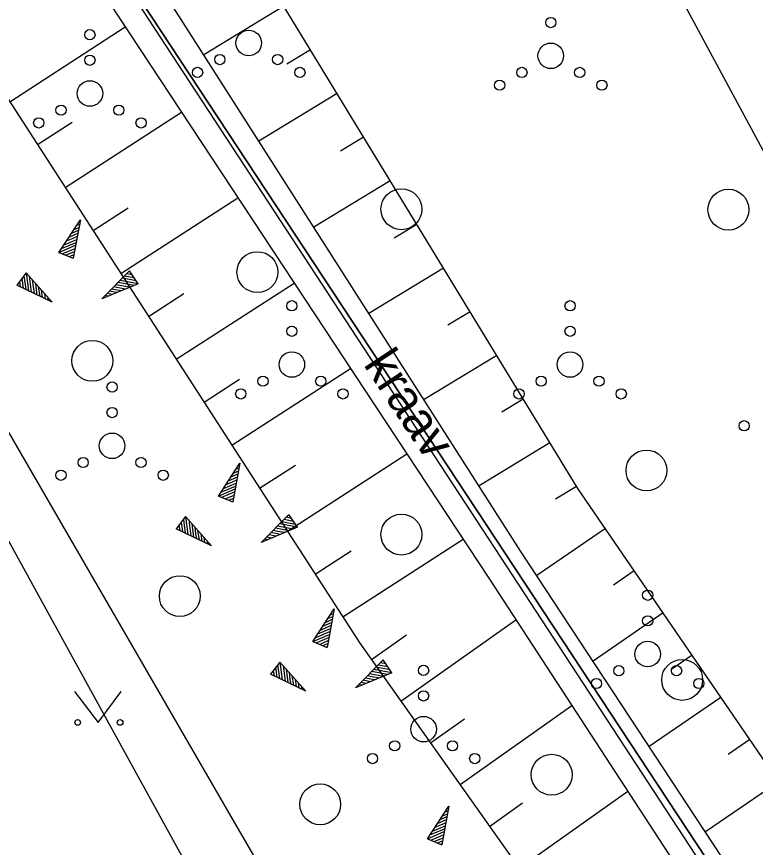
# Model space of a CAD drawing. Extents: x 554947 to 555436, y 6564938 to 6565792.
# Drawn here: x 555242.09 to 555256.53, y 6565114.23 to 6565130.48 of the extents above; entities that cross this region are included whole.
import ezdxf

# ---------------------------------------------------------------- set-up
doc = ezdxf.new("R2010")
doc.units = 0
for name, color, linetype in [('HALJASTUS', 7, 'Continuous'), ('MPKAABEL', 7, 'Continuous'), ('PIIR', 7, 'Continuous'), ('RELJEEF', 7, 'Continuous'), ('VEEKOGU', 7, 'Continuous')]:
    doc.layers.add(name, color=color, linetype=linetype)

msp = doc.modelspace()

# ---------------------------------------------------------------- linework, layer by layer
at = {"layer": 'HALJASTUS'}
for p, q in [((555243.221, 6565117.279), (555243.684, 6565116.673)), ((555243.684, 6565116.673), (555244.13, 6565117.279))]:
    msp.add_line(p, q, dxfattribs=at)
for points in [[(555235.12, 6565151.155), (555232.135, 6565148.949), (555229.151, 6565146.49), (555228.521, 6565144.196), (555233.66, 6565136.637), (555246.422, 6565114.586), (555255.514, 6565098.946)], [(555277.06, 6565106.584), (555277.255, 6565111.788), (555268.557, 6565110.949), (555265.778, 6565110.936), (555262.384, 6565108.727), (555261.075, 6565113.375), (555263.858, 6565115.236), (555262.795, 6565117.659), (555261.001, 6565121.133), (555260.129, 6565122.751), (555257.76, 6565125.864), (555253.762, 6565133.295), (555248.914, 6565136.251)]]:
    msp.add_lwpolyline(points, dxfattribs=at)
for centre, radius in [((555252.534, 6565130.359), 0.1), ((555243.522, 6565130.122), 0.1), ((555246.628, 6565129.96), 0.25), ((555252.534, 6565129.709), 0.25), ((555243.522, 6565129.622), 0.1), ((555246.063, 6565129.635), 0.1), ((555247.193, 6565129.635), 0.1), ((555245.628, 6565129.385), 0.1), ((555247.628, 6565129.385), 0.1), ((555251.969, 6565129.384), 0.1), ((555253.099, 6565129.384), 0.1), ((555243.522, 6565128.972), 0.25), ((555251.534, 6565129.134), 0.1), ((555253.534, 6565129.134), 0.1), ((555242.957, 6565128.647), 0.1), ((555244.087, 6565128.647), 0.1), ((555242.522, 6565128.397), 0.1), ((555244.522, 6565128.397), 0.1), ((555249.614, 6565126.709), 0.4), ((555256.007, 6565126.7), 0.4), ((555246.797, 6565125.479), 0.4), ((555247.471, 6565124.822), 0.1), ((555252.912, 6565124.822), 0.1), ((555247.471, 6565124.322), 0.1), ((555252.912, 6565124.322), 0.1), ((555243.57, 6565123.744), 0.4), ((555247.471, 6565123.672), 0.25), ((555252.912, 6565123.672), 0.25), ((555243.956, 6565123.232), 0.1), ((555246.906, 6565123.347), 0.1), ((555248.036, 6565123.347), 0.1), ((555252.347, 6565123.347), 0.1), ((555253.477, 6565123.347), 0.1), ((555246.471, 6565123.097), 0.1), ((555248.471, 6565123.097), 0.1), ((555251.912, 6565123.097), 0.1), ((555253.912, 6565123.097), 0.1), ((555243.956, 6565122.732), 0.1), ((555256.315, 6565122.475), 0.1), ((555243.956, 6565122.082), 0.25), ((555254.405, 6565121.6), 0.4), ((555243.391, 6565121.757), 0.1), ((555244.521, 6565121.757), 0.1), ((555242.956, 6565121.507), 0.1), ((555244.956, 6565121.507), 0.1), ((555249.614, 6565120.347), 0.4), ((555245.28, 6565119.143), 0.4), ((555254.429, 6565119.16), 0.1), ((555254.429, 6565118.66), 0.1), ((555254.429, 6565118.01), 0.25), ((555255.103, 6565117.505), 0.4), ((555250.047, 6565117.691), 0.1), ((555253.864, 6565117.685), 0.1), ((555254.994, 6565117.685), 0.1), ((555253.429, 6565117.435), 0.1), ((555255.429, 6565117.435), 0.1), ((555250.047, 6565117.191), 0.1), ((555243.283, 6565116.673), 0.055), ((555244.112, 6565116.673), 0.055), ((555250.047, 6565116.541), 0.25), ((555249.482, 6565116.216), 0.1), ((555250.612, 6565116.216), 0.1), ((555249.047, 6565115.966), 0.1), ((555251.047, 6565115.966), 0.1), ((555252.551, 6565115.65), 0.4), ((555248.025, 6565115.071), 0.4)]:
    msp.add_circle(centre, radius, dxfattribs=at)
at = {"layer": 'MPKAABEL'}
msp.add_lwpolyline([(555252.588, 6565101.946), (555250.157, 6565105.485), (555246.43, 6565112.048), (555243.328, 6565117.686), (555240.248, 6565123.284), (555235.885, 6565131.607), (555233.393, 6565136.173), (555233.034, 6565137.981), (555233.62, 6565138.358), (555237.1, 6565137.907), (555242.704, 6565136.954), (555245.573, 6565136.455), (555256.506, 6565134.49), (555262.887, 6565133.288), (555269.268, 6565132.087), (555280.849, 6565129.896), (555289.168, 6565128.301), (555288.207, 6565123.189), (555286.959, 6565118.589), (555293.983, 6565117.646), (555297.167, 6565117.091)], dxfattribs=at)
at = {"layer": 'PIIR'}
for points in [[(555293.54, 6565286.23), (555256.63, 6565245.54), (555254.61, 6565228.5), (555255.75, 6565226.79), (555261.42, 6565218.27), (555289.11, 6565186.6), (555315.28, 6565149.09), (555315.73, 6565134.86), (555310.07, 6565124.47), (555303.59, 6565115.89), (555291.54, 6565100.48), (555288.85, 6565092.31), (555275.41, 6565088.83), (555273.15, 6565087.34), (555239.11, 6565139), (555231.12, 6565150.64), (555225.89, 6565157.13), (555173.21, 6565166.35), (555173.84, 6565168.77), (555191.64, 6565237.48), (555195.28, 6565271.63)], [(555272.013, 6565013.369), (555140.74, 6565041.04), (555172.58, 6565163.93), (555173.21, 6565166.35), (555225.89, 6565157.13), (555231.12, 6565150.64), (555239.11, 6565139), (555273.15, 6565087.34), (555275.41, 6565088.83), (555288.85, 6565092.31), (555289.83, 6565088.53), (555290.166, 6565088.221)]]:
    msp.add_lwpolyline(points, dxfattribs=at)
at = {"layer": 'RELJEEF'}
for p, q in [((555247.314, 6565130.683), (555245.748, 6565129.729)), ((555241.954, 6565128.812), (555244.214, 6565130.273)), ((555247.834, 6565129.829), (555247.37, 6565129.546)), ((555248.355, 6565128.975), (555246.825, 6565128.043)), ((555243.04, 6565127.133), (555245.315, 6565128.604)), ((555242.497, 6565127.973), (555243.177, 6565128.412)), ((555248.875, 6565128.121), (555248.421, 6565127.845)), ((555249.395, 6565127.267), (555247.902, 6565126.357)), ((555244.125, 6565125.453), (555246.416, 6565126.934)), ((555243.583, 6565126.293), (555244.267, 6565126.736)), ((555242.917, 6565125.864), (555243.337, 6565126.504)), ((555243.337, 6565126.504), (555243.197, 6565125.749)), ((555243.262, 6565126.389), (555243.322, 6565126.414)), ((555243.312, 6565126.464), (555243.332, 6565126.474)), ((555249.916, 6565126.413), (555249.473, 6565126.143)), ((555243.167, 6565126.239), (555243.297, 6565126.299)), ((555243.212, 6565126.314), (555243.312, 6565126.354)), ((555243.017, 6565126.014), (555243.267, 6565126.119)), ((555243.067, 6565126.089), (555243.192, 6565126.144)), ((555243.117, 6565126.164), (555243.287, 6565126.239)), ((555243.192, 6565126.144), (555243.277, 6565126.179)), ((555242.917, 6565125.864), (555243.242, 6565126.004)), ((555242.967, 6565125.939), (555243.252, 6565126.059)), ((555242.982, 6565125.839), (555243.232, 6565125.944)), ((555242.917, 6565125.864), (555243.197, 6565125.749)), ((555242.917, 6565125.864), (555242.917, 6565125.864)), ((555243.047, 6565125.809), (555243.222, 6565125.884)), ((555243.117, 6565125.784), (555243.212, 6565125.824)), ((555243.182, 6565125.759), (555243.197, 6565125.764)), ((555242.276, 6565125.463), (555242.091, 6565125.223)), ((555242.276, 6565125.463), (555242.781, 6565124.893)), ((555242.276, 6565125.463), (555242.321, 6565125.113)), ((555242.276, 6565125.463), (555242.276, 6565125.463)), ((555243.755, 6565124.958), (555244.295, 6565125.503)), ((555244.345, 6565125.428), (555244.245, 6565125.448)), ((555244.305, 6565125.488), (555244.285, 6565125.488)), ((555244.465, 6565125.253), (555244.295, 6565125.503)), ((555250.436, 6565125.559), (555248.978, 6565124.671)), ((555242.146, 6565125.293), (555242.161, 6565125.193)), ((555242.191, 6565125.353), (555242.216, 6565125.168)), ((555242.231, 6565125.408), (555242.266, 6565125.138)), ((555242.336, 6565125.398), (555242.376, 6565125.088)), ((555242.396, 6565125.328), (555242.431, 6565125.063)), ((555244.38, 6565125.218), (555244.075, 6565125.278)), ((555244.465, 6565125.253), (555244.115, 6565125.318)), ((555244.425, 6565125.308), (555244.16, 6565125.363)), ((555244.385, 6565125.368), (555244.2, 6565125.403)), ((555242.781, 6565124.893), (555242.091, 6565125.223)), ((555242.101, 6565125.238), (555242.106, 6565125.218)), ((555242.456, 6565125.263), (555242.471, 6565125.123)), ((555242.471, 6565125.123), (555242.486, 6565125.033)), ((555242.511, 6565125.193), (555242.541, 6565125.008)), ((555242.571, 6565125.128), (555242.591, 6565124.983)), ((555244.465, 6565125.253), (555243.755, 6565124.958)), ((555244.045, 6565125.078), (555243.905, 6565125.108)), ((555244.13, 6565125.113), (555243.945, 6565125.148)), ((555244.08, 6565125.173), (555243.99, 6565125.193)), ((555244.295, 6565125.183), (555244.03, 6565125.233)), ((555244.215, 6565125.148), (555244.08, 6565125.173)), ((555244.465, 6565125.253), (555244.465, 6565125.253)), ((555245.211, 6565123.774), (555247.517, 6565125.264)), ((555242.631, 6565125.058), (555242.646, 6565124.958)), ((555242.691, 6565124.993), (555242.701, 6565124.928)), ((555243.795, 6565124.973), (555243.78, 6565124.978)), ((555243.88, 6565125.008), (555243.82, 6565125.023)), ((555243.965, 6565125.043), (555243.86, 6565125.063)), ((555244.668, 6565124.613), (555245.358, 6565125.059)), ((555242.751, 6565124.923), (555242.756, 6565124.903)), ((555250.956, 6565124.705), (555250.524, 6565124.442)), ((555251.477, 6565123.851), (555250.055, 6565122.985)), ((555246.297, 6565122.094), (555248.619, 6565123.595)), ((555245.754, 6565122.934), (555246.448, 6565123.383)), ((555251.997, 6565122.997), (555251.576, 6565122.741)), ((555252.517, 6565122.143), (555251.132, 6565121.299)), ((555247.383, 6565120.414), (555249.72, 6565121.925)), ((555246.035, 6565121.1), (555246.455, 6565121.74)), ((555246.455, 6565121.74), (555246.315, 6565120.985)), ((555246.43, 6565121.7), (555246.45, 6565121.71)), ((555246.84, 6565121.254), (555247.539, 6565121.706)), ((555246.285, 6565121.475), (555246.415, 6565121.535)), ((555246.33, 6565121.55), (555246.43, 6565121.59)), ((555246.38, 6565121.625), (555246.44, 6565121.65)), ((555246.185, 6565121.325), (555246.31, 6565121.38)), ((555246.235, 6565121.4), (555246.405, 6565121.475)), ((555246.31, 6565121.38), (555246.395, 6565121.415)), ((555246.035, 6565121.1), (555246.36, 6565121.24)), ((555246.085, 6565121.175), (555246.37, 6565121.295)), ((555246.135, 6565121.25), (555246.385, 6565121.355)), ((555253.038, 6565121.289), (555252.627, 6565121.039)), ((555246.035, 6565121.1), (555246.315, 6565120.985)), ((555246.035, 6565121.1), (555246.035, 6565121.1)), ((555246.1, 6565121.075), (555246.35, 6565121.18)), ((555246.165, 6565121.045), (555246.34, 6565121.12)), ((555246.235, 6565121.02), (555246.33, 6565121.06)), ((555246.3, 6565120.995), (555246.315, 6565121)), ((555246.873, 6565120.194), (555247.413, 6565120.739)), ((555247.423, 6565120.724), (555247.403, 6565120.724)), ((555247.583, 6565120.489), (555247.413, 6565120.739)), ((555245.394, 6565120.699), (555245.209, 6565120.459)), ((555245.309, 6565120.589), (555245.334, 6565120.404)), ((555245.349, 6565120.644), (555245.384, 6565120.374)), ((555245.394, 6565120.699), (555245.899, 6565120.129)), ((555245.394, 6565120.699), (555245.439, 6565120.349)), ((555245.394, 6565120.699), (555245.394, 6565120.699)), ((555245.454, 6565120.634), (555245.494, 6565120.324)), ((555245.514, 6565120.564), (555245.549, 6565120.299)), ((555247.543, 6565120.544), (555247.278, 6565120.599)), ((555247.503, 6565120.604), (555247.318, 6565120.639)), ((555247.463, 6565120.664), (555247.363, 6565120.684)), ((555245.899, 6565120.129), (555245.209, 6565120.459)), ((555245.219, 6565120.474), (555245.224, 6565120.454)), ((555245.264, 6565120.529), (555245.279, 6565120.429)), ((555245.574, 6565120.499), (555245.589, 6565120.359)), ((555245.629, 6565120.429), (555245.659, 6565120.244)), ((555247.583, 6565120.489), (555246.873, 6565120.194)), ((555247.198, 6565120.409), (555247.108, 6565120.429)), ((555247.413, 6565120.419), (555247.148, 6565120.469)), ((555247.498, 6565120.454), (555247.193, 6565120.514)), ((555247.333, 6565120.384), (555247.198, 6565120.409)), ((555247.583, 6565120.489), (555247.233, 6565120.554)), ((555247.583, 6565120.489), (555247.583, 6565120.489)), ((555253.601, 6565120.463), (555252.262, 6565119.545)), ((555245.589, 6565120.359), (555245.604, 6565120.269)), ((555245.689, 6565120.364), (555245.709, 6565120.219)), ((555245.749, 6565120.294), (555245.764, 6565120.194)), ((555246.998, 6565120.244), (555246.938, 6565120.259)), ((555247.083, 6565120.279), (555246.978, 6565120.299)), ((555247.163, 6565120.314), (555247.023, 6565120.344)), ((555247.248, 6565120.349), (555247.063, 6565120.384)), ((555248.469, 6565118.735), (555250.821, 6565120.256)), ((555245.809, 6565120.229), (555245.819, 6565120.164)), ((555245.869, 6565120.159), (555245.874, 6565120.139)), ((555246.913, 6565120.209), (555246.898, 6565120.214)), ((555247.926, 6565119.575), (555248.629, 6565120.029)), ((555254.166, 6565119.638), (555253.76, 6565119.359)), ((555247.879, 6565118.255), (555248.299, 6565118.895)), ((555248.299, 6565118.895), (555248.159, 6565118.14)), ((555248.224, 6565118.78), (555248.284, 6565118.805)), ((555248.274, 6565118.855), (555248.294, 6565118.865)), ((555254.731, 6565118.813), (555253.361, 6565117.874)), ((555248.079, 6565118.555), (555248.249, 6565118.63)), ((555248.129, 6565118.63), (555248.259, 6565118.69)), ((555248.174, 6565118.705), (555248.274, 6565118.745)), ((555249.603, 6565117.088), (555251.853, 6565118.681)), ((555247.929, 6565118.33), (555248.214, 6565118.45)), ((555247.979, 6565118.405), (555248.229, 6565118.51)), ((555248.029, 6565118.48), (555248.154, 6565118.535)), ((555248.154, 6565118.535), (555248.239, 6565118.57)), ((555247.879, 6565118.255), (555248.204, 6565118.395)), ((555247.944, 6565118.23), (555248.194, 6565118.335)), ((555249.025, 6565117.904), (555249.71, 6565118.389)), ((555247.879, 6565118.255), (555248.159, 6565118.14)), ((555247.879, 6565118.255), (555247.879, 6565118.255)), ((555248.009, 6565118.2), (555248.184, 6565118.275)), ((555248.079, 6565118.175), (555248.174, 6565118.215)), ((555248.144, 6565118.15), (555248.159, 6565118.155)), ((555255.297, 6565117.988), (555254.881, 6565117.703)), ((555247.238, 6565117.854), (555247.053, 6565117.614)), ((555247.193, 6565117.799), (555247.228, 6565117.529)), ((555247.238, 6565117.854), (555247.743, 6565117.284)), ((555247.238, 6565117.854), (555247.283, 6565117.504)), ((555247.238, 6565117.854), (555247.238, 6565117.854)), ((555248.717, 6565117.349), (555249.257, 6565117.894)), ((555249.307, 6565117.819), (555249.207, 6565117.839)), ((555249.267, 6565117.879), (555249.247, 6565117.879)), ((555249.427, 6565117.644), (555249.257, 6565117.894)), ((555247.108, 6565117.684), (555247.123, 6565117.584)), ((555247.153, 6565117.744), (555247.178, 6565117.559)), ((555247.298, 6565117.789), (555247.338, 6565117.479)), ((555247.358, 6565117.719), (555247.393, 6565117.454)), ((555247.418, 6565117.654), (555247.433, 6565117.514)), ((555249.427, 6565117.644), (555248.717, 6565117.349)), ((555249.342, 6565117.609), (555249.037, 6565117.669)), ((555249.427, 6565117.644), (555249.077, 6565117.709)), ((555249.387, 6565117.699), (555249.122, 6565117.754)), ((555249.347, 6565117.759), (555249.162, 6565117.794)), ((555249.427, 6565117.644), (555249.427, 6565117.644)), ((555247.743, 6565117.284), (555247.053, 6565117.614)), ((555247.063, 6565117.629), (555247.068, 6565117.609)), ((555247.433, 6565117.514), (555247.448, 6565117.424)), ((555247.473, 6565117.584), (555247.503, 6565117.399)), ((555247.533, 6565117.519), (555247.553, 6565117.374)), ((555249.007, 6565117.469), (555248.867, 6565117.499)), ((555249.092, 6565117.504), (555248.907, 6565117.539)), ((555249.042, 6565117.564), (555248.952, 6565117.584)), ((555249.257, 6565117.574), (555248.992, 6565117.624)), ((555249.177, 6565117.539), (555249.042, 6565117.564)), ((555247.593, 6565117.449), (555247.608, 6565117.349)), ((555247.653, 6565117.384), (555247.663, 6565117.319)), ((555247.713, 6565117.314), (555247.718, 6565117.294)), ((555248.757, 6565117.364), (555248.742, 6565117.369)), ((555248.842, 6565117.399), (555248.782, 6565117.414)), ((555248.927, 6565117.434), (555248.822, 6565117.454)), ((555255.862, 6565117.163), (555254.46, 6565116.202)), ((555250.759, 6565115.456), (555252.946, 6565117.005)), ((555250.181, 6565116.272), (555250.847, 6565116.743)), ((555256.427, 6565116.338), (555256.002, 6565116.047)), ((555256.993, 6565115.514), (555255.559, 6565114.531)), ((555251.915, 6565113.824), (555254.038, 6565115.328)), ((555250.122, 6565114.397), (555250.542, 6565115.037)), ((555250.542, 6565115.037), (555250.402, 6565114.282)), ((555251.337, 6565114.64), (555251.984, 6565115.098)), ((555250.417, 6565114.847), (555250.517, 6565114.887)), ((555250.467, 6565114.922), (555250.527, 6565114.947)), ((555250.517, 6565114.997), (555250.537, 6565115.007)), ((555250.322, 6565114.697), (555250.492, 6565114.772)), ((555250.372, 6565114.772), (555250.502, 6565114.832)), ((555250.397, 6565114.677), (555250.482, 6565114.712)), ((555250.172, 6565114.472), (555250.457, 6565114.592)), ((555250.222, 6565114.547), (555250.472, 6565114.652)), ((555250.272, 6565114.622), (555250.397, 6565114.677)), ((555250.122, 6565114.397), (555250.447, 6565114.537)), ((555250.122, 6565114.397), (555250.402, 6565114.282)), ((555250.122, 6565114.397), (555250.122, 6565114.397)), ((555250.187, 6565114.372), (555250.437, 6565114.477)), ((555250.252, 6565114.342), (555250.427, 6565114.417)), ((555250.322, 6565114.317), (555250.417, 6565114.357)), ((555250.387, 6565114.292), (555250.402, 6565114.297))]:
    msp.add_line(p, q, dxfattribs=at)
msp.add_lwpolyline([(555267.243, 6565100.718), (555264.574, 6565104.451), (555253.061, 6565121.25), (555242.65, 6565138.338), (555234.145, 6565148.829), (555233.386, 6565148.636), (555231.367, 6565148.23), (555230.85, 6565146.543), (555236.09, 6565137.882), (555248.799, 6565118.225), (555259.289, 6565103.411), (555261.934, 6565099.868)], dxfattribs=at)
at = {"layer": 'VEEKOGU'}
for points in [[(555265.45, 6565099.986), (555262.604, 6565103.817), (555251.937, 6565120.038), (555239.993, 6565138.74), (555233.721, 6565147.576), (555233.071, 6565146.869), (555239.071, 6565138.07), (555251.323, 6565119.495), (555261.764, 6565103.47), (555264.187, 6565099.861)], [(555239.299, 6565138.626), (555251.662, 6565119.733), (555262.176, 6565103.668)]]:
    msp.add_lwpolyline(points, dxfattribs=at)

# ---------------------------------------------------------------- texts
msp.add_text('kraav', height=0.7, rotation=303.3628, dxfattribs=at).set_placement((555248.858, 6565123.676))

doc.saveas('drawing.dxf')
